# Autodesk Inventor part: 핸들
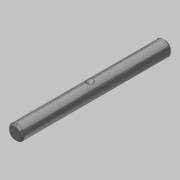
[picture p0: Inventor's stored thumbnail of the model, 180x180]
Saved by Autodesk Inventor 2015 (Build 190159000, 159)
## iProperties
Created: 2019-04
Part Number: 핸들
Material: 스테인리스강
Document SubType Name: Modeling
Designer: mduedu
Density: 1 g/cm^3
Appearance: 반광택
Author: mduedu
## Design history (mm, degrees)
sketch "스케치1"
  geometry: C1 r 4 at (0, 0); 1 further point
  constraints: 1 centre point, 1 coincident
  dimensions: "d0" = 8 diameter of C1
extrude "돌출1" new body sketch "스케치1" stored distance "d1" = 80; taper "d2" = 0 deg
chamfer "모따기1" distance "d3" = 1; stored, may be unused: second distance "d4" = 2, angle "d5" = 45 deg
sketch "스케치2"
  geometry: L1 (-39, 4)-(39, 4) reference; L2 (0, 4)-(0, 2); L3 (0, 2)-(2, 4); L4 (0, 4)-(2, 4); 1 further point
  constraints: 6 end point, 2 perpendicular, 1 midpoint, 1 point on line
  dimensions: "d6" = 4 diameter of L3.end L2; "d8" = 45 deg angle of L3 L2
revolve "회전1" sketch "스케치2" stored, may be unused: angle "d10" = 90 deg
node "작업점1"
  node "작업축1"
  node "작업 평면1"
node "솔리드1"
